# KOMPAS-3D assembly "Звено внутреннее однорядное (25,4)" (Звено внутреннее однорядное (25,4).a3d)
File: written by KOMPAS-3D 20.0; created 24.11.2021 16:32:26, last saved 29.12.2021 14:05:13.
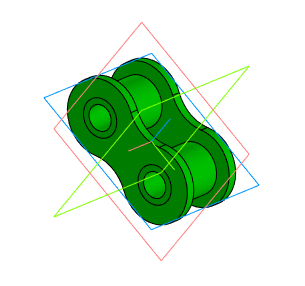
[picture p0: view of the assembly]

Document properties: Полное имя файла: C:\!WORK!\ЗИГ-18.240.00 Линия ЗигЗаг\Цепь\Звено внутреннее однорядное (25,4).a3d

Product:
- Part/product: Звено внутреннее однорядное (25,4)
    Масса: 0.0750693
  - Component [detail]: Пластина внутренняя (25,4)  | qty 2  | Материал: Сталь 45  ГОСТ 1050-2013 (density 7810 kg/m3); Масса: 0.0168549; source file: Пластина внутренняя (25,4).m3d
  - Component [detail]: Ролик (15,88)  | qty 2  | Материал: Сталь 45  ГОСТ 1050-2013 (density 7810 kg/m3); Масса: 0.00968765; source file: Ролик (15,88).m3d
  - Component [detail]: Втулка-ось (22,4)  | qty 2  | Материал: Сталь 45  ГОСТ 1050-2013 (density 7810 kg/m3); Масса: 0.0109921; source file: Втулка-ось (22,4).m3d

Referenced files in C:\!WORK!\ЗИГ-18.240.00 Линия ЗигЗаг\Цепь\: Пластина внутренняя (25,4).m3d, Ролик (15,88).m3d, Втулка-ось (22,4).m3d
Referenced files in C:\!WORK!\ЗИГ-18.240.00\Цепь\: Пластина внутренняя (25,4).m3d, Ролик (15,88).m3d, Втулка-ось (22,4).m3d
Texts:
  Пластина внутренняя (25,4) (1)
  Пластина внутренняя (25,4) (2)
  Ролик (15,88) (1)
  Ролик (15,88) (2)
  Втулка-ось (22,4) (1)
  Втулка-ось (22,4) (2)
